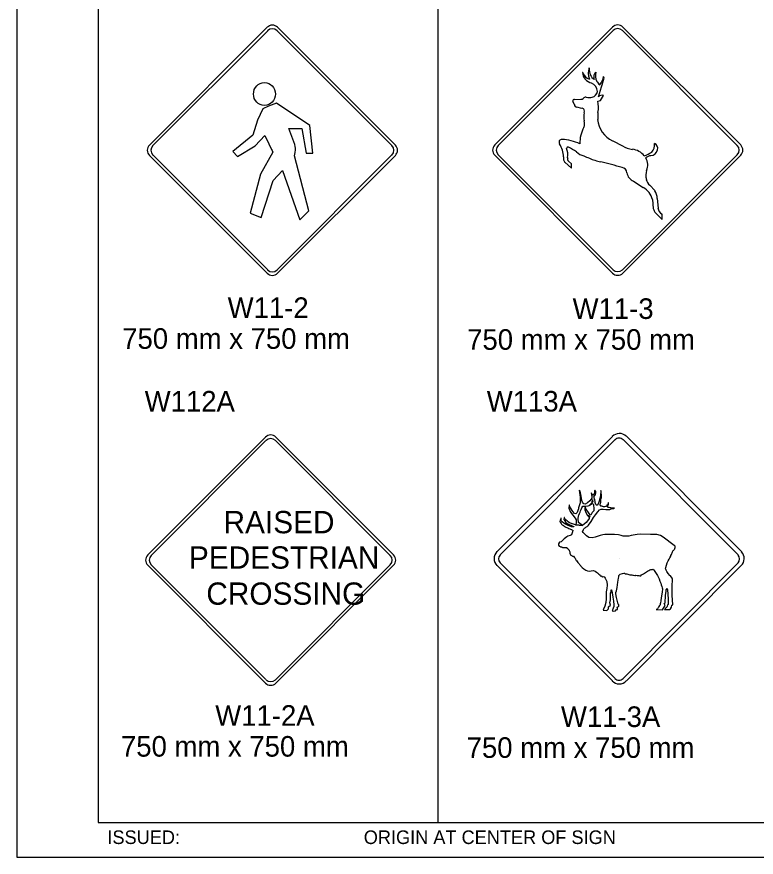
# Model space of a CAD drawing. Extents: x -12 to 6962, y -3756 to 679.
# Drawn here: x 2167.2 to 2275, y -235.4 to -112.9 of the extents above; entities that cross this region are included whole.
import ezdxf

# ---------------------------------------------------------------- set-up
doc = ezdxf.new("R2010")
doc.units = 0
for name, color, linetype in [('Level 1', 7, 'Continuous'), ('Level 2', 7, 'Continuous'), ('Level 3', 7, 'Continuous'), ('Level 62', 7, 'Continuous')]:
    doc.layers.add(name, color=color, linetype=linetype)

msp = doc.modelspace()

# ---------------------------------------------------------------- linework, layer by layer
at = {"layer": 'Level 1'}
for p, q in [((2179.04, -30.35), (2179.04, -230.35)), ((2228.56, -30.35), (2228.56, -230.35)), ((2186.51, -131.6), (2203.69, -114.41)), ((2187.01, -131.66), (2203.76, -114.91)), ((2205.13, -114.91), (2221.88, -131.66)), ((2205.19, -114.41), (2222.38, -131.6)), ((2236.88, -131.57), (2254.07, -114.39)), ((2237.38, -131.63), (2254.13, -114.88)), ((2255.5, -114.88), (2272.25, -131.63)), ((2255.56, -114.39), (2272.75, -131.57)), ((2252.02, -124.54), (2252.45, -123.1)), ((2248.49, -124.96), (2249.45, -124.9)), ((2252.3, -125.07), (2252.74, -124.35)), ((2248.51, -125.68), (2248.27, -125.21)), ((2249.6, -126.23), (2248.83, -126.04)), ((2251.89, -125.19), (2252.3, -125.07)), ((2254.08, -130.98), (2255.49, -131.68)), ((2204.46, -132.23), (2204.46, -132.23)), ((2254.83, -132.2), (2254.83, -132.2)), ((2203.69, -150.28), (2186.51, -133.09)), ((2203.76, -149.78), (2187.01, -133.03)), ((2221.88, -133.03), (2205.13, -149.78)), ((2222.38, -133.1), (2205.19, -150.28)), ((2254.07, -150.25), (2236.88, -133.07)), ((2254.13, -149.75), (2237.38, -133)), ((2272.25, -133), (2255.5, -149.76)), ((2272.75, -133.07), (2255.56, -150.25)), ((2248.08, -134.96), (2247.12, -134.1)), ((2248.08, -134.31), (2247.65, -133.92)), ((2248.08, -134.96), (2248.08, -134.31)), ((2257.12, -136.87), (2258.54, -137.76)), ((2259.49, -137.43), (2260.24, -138.23)), ((2259.88, -139.53), (2260, -140.82)), ((2260.56, -139.36), (2260.69, -140.76)), ((2260.37, -141.5), (2261.29, -142.43)), ((2261.29, -142.43), (2261.29, -141.68)), ((2186.26, -191.34), (2203.45, -174.16)), ((2186.76, -191.4), (2203.51, -174.65)), ((2204.88, -174.65), (2221.63, -191.4)), ((2204.94, -174.16), (2222.13, -191.34)), ((2237.22, -190.83), (2254.03, -174.08)), ((2237.68, -191.34), (2254.44, -174.53)), ((2255.62, -174.53), (2272.38, -191.34)), ((2256.08, -174.02), (2272.89, -190.88)), ((2251.17, -183.89), (2251.29, -183.99)), ((2247.14, -186.11), (2247.07, -185.95)), ((2247.28, -186.26), (2247.14, -186.11)), ((2247.42, -186.38), (2247.28, -186.26)), ((2247.57, -186.53), (2247.42, -186.38)), ((2247.8, -186.64), (2247.57, -186.53)), ((2248.05, -186.74), (2247.8, -186.64)), ((2248.37, -186.87), (2248.05, -186.74)), ((2248.66, -186.95), (2248.37, -186.87)), ((2249.65, -187.05), (2248.66, -186.95)), ((2204.21, -191.97), (2204.21, -191.97)), ((2255.14, -191.85), (2255.14, -191.85)), ((2203.45, -210.02), (2186.26, -192.84)), ((2203.51, -209.52), (2186.76, -192.77)), ((2221.63, -192.77), (2204.88, -209.53)), ((2222.13, -192.84), (2204.94, -210.02)), ((2254.03, -209.69), (2237.22, -192.88)), ((2254.44, -209.33), (2237.68, -192.47)), ((2272.38, -192.47), (2255.62, -209.33)), ((2272.84, -192.88), (2256.08, -209.69)), ((2254.39, -209.33), (2254.42, -209.35)), ((2179.04, -230.35), (2330.8, -230.35))]:
    msp.add_line(p, q, dxfattribs=at)
msp.add_lwpolyline([(2198.69, -132.5), (2199.36, -133.27), (2201.92, -131.68), (2203.35, -130.19), (2204.53, -132.6), (2202.69, -135.83), (2201.2, -141.52), (2202.79, -142.14), (2204.58, -136.75), (2205.92, -135.27), (2208.43, -142.49), (2209.76, -141.16), (2207.66, -133.17), (2207.76, -132.65), (2207.81, -132.3), (2207.81, -132.04), (2207.76, -131.78), (2207.71, -131.48), (2206.84, -129.17), (2208.73, -129.17), (2209.35, -132.76), (2210.32, -132.76), (2209.91, -128.71), (2205.04, -125.48), (2203.87, -125.89), (2203.05, -126.3), (2202.28, -127.94), (2201.61, -130.14)], close=True, dxfattribs=at)
for points in [[(2251.6, -182.11), (2251.55, -182.02), (2251.49, -181.9), (2251.43, -182.03), (2251.43, -182.32), (2251.25, -182.63), (2251.19, -182.64), (2251.16, -182.57), (2251.04, -182.43), (2251, -182.31), (2250.95, -182.26), (2250.98, -182.58), (2251.01, -182.63), (2251.02, -182.7), (2251.05, -183.01), (2251.05, -183.05), (2250.74, -183.45), (2250.39, -183.72), (2250.07, -183.92), (2249.88, -183.9), (2249.83, -183.86), (2249.66, -183.64), (2249.56, -183.38), (2249.48, -182.79), (2249.32, -182.02), (2249.2, -181.88), (2249.34, -182.92), (2249.34, -183.23), (2249.31, -183.44), (2249.32, -183.73), (2249.11, -184.45), (2249.1, -184.6), (2248.99, -184.86), (2248.88, -185.13), (2248.71, -185.35), (2248.51, -185.28), (2248.27, -185.02), (2247.94, -184.45), (2247.83, -184.32), (2247.8, -184.02), (2247.73, -184.1), (2247.7, -184.53), (2247.93, -185.08), (2248.62, -185.98), (2248.73, -186.21), (2248.73, -186.75), (2248.65, -186.95), (2249.66, -187.05), (2249.08, -186.6), (2249.02, -186.05), (2249.07, -185.62), (2249.13, -185.52), (2249.22, -185.29), (2249.32, -185.09), (2249.38, -184.93), (2249.47, -184.72), (2249.56, -184.47), (2249.71, -184.21), (2249.83, -184.23), (2250.18, -184.24), (2250.49, -184.19), (2250.66, -184.12), (2251.06, -183.69), (2251.14, -183.27), (2251.11, -183.32), (2251.12, -183.39), (2251.11, -183.45), (2251.12, -183.5), (2251.06, -183.7), (2251.05, -183.71), (2251.17, -183.57), (2251.17, -183.59), (2251.17, -183.59), (2250.68, -184.09), (2251.09, -183.85), (2251.17, -183.89)], [(2253.47, -183.73), (2253.47, -183.71), (2253.46, -183.7), (2253.42, -183.74), (2253.42, -183.8), (2253.42, -183.83), (2253.41, -183.88), (2253.36, -183.95), (2253.3, -184.02), (2253.24, -184.1), (2253.17, -184.18), (2253.15, -184.21), (2253.06, -184.28), (2253.03, -184.28), (2252.88, -184.3), (2252.88, -184.3), (2252.78, -184.3), (2252.76, -184.3), (2252.64, -184.29), (2252.57, -184.27), (2252.49, -184.25), (2252.46, -184.24), (2252.41, -184.22), (2252.36, -184.21), (2252.32, -184.18), (2252.29, -184.12), (2252.27, -184.1), (2252.27, -184.07), (2252.25, -184.03), (2252.25, -183.99), (2252.26, -183.93), (2252.29, -183.86), (2252.31, -183.76), (2252.34, -183.7), (2252.35, -183.62), (2252.36, -183.52), (2252.36, -183.43), (2252.36, -183.31), (2252.36, -183.2), (2252.37, -183.1), (2252.43, -183.04), (2252.43, -182.96), (2252.43, -182.75), (2252.43, -182.73), (2252.43, -182.64), (2252.43, -182.52), (2252.42, -182.41), (2252.42, -182.3), (2252.41, -182.21), (2252.39, -182.09), (2252.36, -182.01), (2252.35, -181.92), (2252.35, -181.92), (2252.35, -181.92), (2252.35, -181.99), (2252.35, -182.06), (2252.35, -182.11), (2252.34, -182.21), (2252.34, -182.24), (2252.34, -182.36), (2252.31, -182.45), (2252.28, -182.58), (2252.28, -182.67), (2252.28, -182.79), (2252.25, -182.88), (2252.23, -182.97), (2252.2, -183.1), (2252.18, -183.17), (2252.16, -183.23), (2252.14, -183.33), (2252.09, -183.5), (2251.98, -183.87), (2251.97, -183.87), (2251.94, -183.93), (2251.9, -183.98), (2251.87, -184.04), (2251.85, -184.08), (2251.78, -184.1), (2251.76, -184.1), (2251.7, -184.1), (2251.64, -183.96), (2251.55, -183.83), (2251.51, -183.69), (2251.51, -183.6), (2251.5, -183.5), (2251.48, -183.4), (2251.46, -183.29), (2251.42, -183.18), (2251.39, -183.04), (2251.38, -182.99), (2251.36, -182.92), (2251.34, -182.84), (2251.37, -182.79), (2251.42, -182.71), (2251.5, -182.63), (2251.55, -182.52), (2251.57, -182.41), (2251.6, -182.33), (2251.6, -182.23), (2251.6, -182.17), (2251.6, -182.11)], [(2262.02, -192.51), (2262.19, -192.19), (2262.3, -191.97), (2262.42, -191.77), (2262.57, -191.54), (2262.58, -191.43), (2262.64, -191.27), (2262.68, -191.12), (2262.74, -191.02), (2262.81, -190.9), (2262.86, -190.8), (2262.92, -190.7), (2262.98, -190.65), (2263.05, -190.55), (2263.14, -190.45), (2263.15, -190.42), (2263.16, -190.37), (2263.17, -190.3), (2263.18, -190.22), (2263.18, -190.14), (2263.18, -190.06), (2263.12, -190.01), (2263.06, -189.98), (2261.43, -188.74), (2261.03, -188.48), (2260.51, -188.35), (2259.61, -188.34), (2258.1, -188.33), (2257.63, -188.37), (2257.07, -188.47), (2256.75, -188.5), (2256.43, -188.61), (2255.61, -188.59), (2255.3, -188.52), (2254.93, -188.41), (2254.35, -188.37), (2253.28, -188.35), (2252.92, -188.37), (2252.63, -188.41), (2252.25, -188.49), (2251.98, -188.61), (2251.5, -188.77), (2251.08, -188.85), (2250.62, -188.8), (2250.25, -188.54), (2250.06, -188.35), (2249.97, -188.25), (2249.88, -188.14), (2249.82, -188.13), (2249.73, -188.07), (2249.7, -188), (2249.69, -187.88), (2249.76, -187.76), (2249.83, -187.63), (2249.87, -187.52), (2249.95, -187.43), (2250.04, -187.39), (2250.18, -187.29), (2250.24, -187.25), (2250.36, -187.17), (2250.43, -187.09), (2250.54, -187.05), (2250.56, -187.02), (2250.96, -186.46), (2251.29, -185.87), (2251.56, -185.47), (2251.92, -185.04), (2252.13, -184.76), (2252.38, -184.67), (2252.71, -184.64), (2253.09, -184.69), (2253.39, -184.71), (2253.68, -184.7), (2253.84, -184.63), (2254.05, -184.59), (2254.23, -184.55), (2254.29, -184.54), (2254.32, -184.52), (2254.33, -184.52), (2254.33, -184.51), (2254.2, -184.5), (2254.02, -184.5), (2253.89, -184.5), (2253.81, -184.49), (2253.73, -184.45), (2253.58, -184.44), (2253.48, -184.42), (2253.41, -184.4), (2253.39, -184.38), (2253.35, -184.33), (2253.34, -184.31), (2253.34, -184.27), (2253.34, -184.22), (2253.35, -184.17), (2253.39, -184.11), (2253.43, -184.07), (2253.47, -183.96), (2253.47, -183.9), (2253.47, -183.84), (2253.47, -183.77), (2253.47, -183.73)], [(2251.29, -183.99), (2251.33, -184.67), (2251.33, -184.66), (2251.33, -184.67), (2251.33, -184.82), (2251.31, -184.89), (2251.31, -184.89), (2251.22, -184.98), (2251.07, -185.13), (2250.88, -185.52), (2250.78, -185.51), (2250.32, -184.79), (2250.23, -184.67), (2250.15, -184.47), (2250.09, -184.47), (2250.07, -184.4), (2250.01, -184.41), (2250.01, -184.51), (2250, -184.64), (2250, -184.75), (2250.16, -185.14), (2250.42, -185.58), (2250.77, -185.75), (2250.41, -185.56), (2250.63, -185.9), (2250.64, -186.02), (2250.55, -186.19), (2250.21, -186.63), (2249.65, -187.05)], [(2247.07, -185.95), (2247.05, -185.9), (2246.98, -185.9), (2246.97, -186.17), (2247.08, -186.36), (2247.24, -186.59), (2247.42, -186.73), (2247.62, -186.86), (2247.84, -186.93), (2248, -187.01), (2248.18, -187.1), (2248.27, -187.16), (2248.37, -187.19), (2248.4, -187.19), (2248.4, -187.26), (2248.09, -187.23), (2247.58, -187.05), (2247.2, -186.85), (2246.94, -186.7), (2246.73, -186.52), (2246.57, -186.36), (2246.56, -186), (2246.51, -186), (2246.45, -186.15), (2246.41, -186.29), (2246.38, -186.44), (2246.42, -186.55), (2246.46, -186.63), (2246.54, -186.76), (2246.61, -186.85), (2246.7, -186.93), (2246.79, -187.01), (2246.88, -187.04), (2246.97, -187.1), (2247.09, -187.18), (2247.15, -187.23), (2247.26, -187.28), (2247.38, -187.34), (2247.53, -187.38), (2247.67, -187.46), (2247.81, -187.52), (2247.92, -187.57), (2248.06, -187.62), (2248.12, -187.67), (2248.23, -187.71), (2248.25, -187.74), (2248.23, -187.99), (2248.11, -188.24), (2248.05, -188.39), (2247.87, -188.5), (2247.53, -188.62), (2247.39, -188.69), (2247.02, -188.99), (2246.76, -189.25), (2246.57, -189.43), (2246.34, -189.49), (2246.17, -189.72), (2246.17, -189.9), (2246.29, -190.08), (2246.41, -190.13), (2246.48, -190.16), (2246.66, -190.16), (2246.67, -190.2), (2246.78, -190.26), (2247.13, -190.23), (2247.33, -190.25), (2247.55, -190.4), (2247.6, -190.48), (2247.66, -190.58), (2247.72, -190.65), (2247.75, -190.71), (2247.78, -190.8), (2247.81, -190.9), (2247.81, -190.97), (2247.81, -191.04), (2247.85, -191.16), (2247.87, -191.19), (2247.89, -191.22), (2247.94, -191.31), (2247.96, -191.35), (2248, -191.39), (2248.07, -191.42), (2248.08, -191.44), (2248.17, -191.48), (2248.18, -191.49), (2248.23, -191.5), (2248.26, -191.5), (2248.3, -191.5), (2248.34, -191.5), (2248.36, -191.5), (2248.37, -191.5), (2248.44, -191.64), (2248.61, -191.82), (2248.67, -191.94), (2248.77, -192.13), (2248.82, -192.17), (2248.99, -192.43), (2249.19, -192.65), (2249.24, -192.71), (2249.64, -193.16), (2249.88, -193.38)], [(2249.88, -193.38), (2250.14, -193.56), (2250.41, -193.65), (2250.68, -193.68), (2250.93, -193.66), (2251.27, -193.61), (2251.53, -193.7), (2251.73, -193.84), (2251.88, -193.96), (2252.07, -194.15), (2252.18, -194.23), (2252.22, -194.29), (2252.25, -194.33), (2252.25, -194.38), (2252.4, -194.36), (2252.65, -194.51), (2252.79, -194.49), (2252.89, -194.59), (2252.97, -194.74), (2253.22, -195.23), (2253.25, -195.74), (2253.2, -196.24), (2253.15, -196.73), (2253.11, -197.72), (2253.1, -198.28), (2252.91, -198.8), (2252.75, -199.23), (2252.68, -199.39), (2253.23, -199.44), (2253.47, -199.17), (2253.46, -198.91), (2253.74, -198.67), (2253.65, -198.34), (2253.74, -197.9), (2253.77, -197.24), (2253.76, -196.92), (2253.84, -196.76), (2253.85, -196.53), (2253.87, -196.42), (2253.89, -196.4), (2253.99, -196.86), (2254.1, -197.47), (2254.18, -198.1), (2254.26, -198.63), (2254.22, -198.84), (2254.15, -199.12), (2254.1, -199.26), (2254.06, -199.34), (2254.06, -199.39), (2253.99, -199.5), (2254.26, -199.54), (2254.48, -199.5), (2254.57, -199.32), (2254.69, -199.28), (2254.76, -199.28), (2254.76, -199.02), (2254.73, -198.99), (2254.74, -198.95), (2254.85, -198.91), (2254.94, -198.85), (2254.99, -198.79), (2254.99, -198.76), (2254.98, -198.66), (2254.95, -198.58), (2254.9, -198.5), (2254.74, -197.95), (2254.63, -197.55), (2254.6, -197.28), (2254.55, -196.94), (2254.55, -196.82), (2254.62, -196.55), (2254.71, -196.06), (2254.83, -195.33), (2254.92, -194.73), (2254.95, -194.51), (2254.98, -194.33), (2255.06, -194.23), (2255.11, -194.18), (2255.17, -194.16)], [(2255.17, -194.16), (2255.51, -194.05), (2255.68, -194), (2255.79, -194.01), (2255.88, -194.08), (2256, -194.08), (2256.13, -194.09), (2256.27, -194.16), (2256.42, -194.2), (2256.56, -194.23), (2256.71, -194.24), (2256.86, -194.26), (2257, -194.27), (2257.12, -194.29), (2257.29, -194.33), (2257.39, -194.33), (2257.47, -194.3), (2257.67, -194.31), (2257.79, -194.31), (2257.88, -194.34), (2258.04, -194.37), (2258.13, -194.39), (2258.17, -194.39), (2258.29, -194.22), (2258.57, -194.07), (2258.86, -193.88), (2259.17, -193.72), (2259.33, -193.59), (2259.51, -193.53), (2259.66, -193.47), (2259.73, -193.46), (2259.82, -193.46), (2259.87, -193.44), (2259.96, -193.41), (2260.12, -193.59), (2260.34, -193.9), (2260.61, -194.32), (2260.84, -194.83), (2260.97, -195.14), (2261.08, -195.47), (2261.15, -195.7), (2261.24, -195.93), (2261.31, -196.14), (2261.34, -196.3), (2261.31, -196.74), (2261.14, -197.59), (2261.11, -198.05), (2261.07, -198.3), (2261.02, -198.46), (2260.98, -198.59), (2260.92, -198.72), (2260.83, -198.86), (2260.75, -198.99), (2260.67, -199.1), (2260.6, -199.17), (2260.55, -199.23), (2260.44, -199.3), (2261.32, -199.32), (2261.72, -198.73), (2261.58, -198.44), (2261.71, -198.32), (2261.78, -197.24), (2261.86, -196.62), (2261.87, -196.41), (2262, -196.22), (2262.03, -196.28), (2262.07, -196.44), (2262.16, -197.73), (2262.15, -198.54), (2262.06, -198.63), (2262.02, -198.81), (2261.95, -198.96), (2261.91, -199.02), (2261.83, -199.07), (2261.79, -199.14), (2261.76, -199.16), (2261.72, -199.24), (2261.69, -199.25), (2261.64, -199.3), (2262.37, -199.29), (2262.52, -199.19), (2262.64, -198.94), (2262.68, -198.67), (2262.83, -198.6), (2262.75, -197.22), (2262.74, -196.28), (2262.73, -195.64), (2262.81, -195.15), (2262.8, -194.88), (2262.73, -194.73), (2262.67, -194.6), (2262.61, -194.51), (2262.5, -194.39), (2262.4, -194.34), (2262.16, -194.03), (2261.95, -193.75), (2261.88, -193.54), (2261.82, -193.43), (2261.8, -193.38), (2261.83, -193.16), (2262.02, -192.51)]]:
    msp.add_lwpolyline(points, dxfattribs=at)
for centre, radius, start, end in [((2204.44, -115.16), 1.06, 45, 135), ((2204.44, -115.6), 0.969, 45, 135), ((2254.81, -115.13), 1.06, 45, 135), ((2254.81, -115.57), 0.969, 45, 135), ((2251.43, -120.8), 1.79, 186.2879, 255.6045), ((2249.62, -121.19), 0.201, 30.1048, 80.5121), ((2250.92, -120.83), 1.16, 193.2507, 257.6268), ((2253.04, -121.08), 2.52, 162.0635, 200.2931), ((2250.55, -120.39), 0.123, 347.4048, 46.932), ((2252.42, -120.61), 1.76, 173.8726, 234.3252), ((2252.35, -121.65), 1.04, 153.1097, 202.0619), ((2252.83, -121.98), 1.61, 139.8512, 150.2463), ((2253.97, -121.35), 2.41, 170.1883, 203.1194), ((2253.76, -121.04), 2.37, 212.0666, 228.2156), ((2250.43, -121.29), 2.32, 319.129, 352.9872), ((2242.97, -119.6), 10.1, 339.7331, 347.2939), ((2252.48, -121.8), 0.34, 356.6035, 43.1712), ((2250.45, -123.85), 1.42, 3.413, 67.7627), ((2248.45, -125.14), 0.19, 75.6178, 199.8309), ((2249.48, -124.46), 0.442, 265.6838, 309.921), ((2250.11, -125.01), 0.411, 75.3801, 148.2178), ((2250.65, -122.1), 2.56, 260.3156, 279.6844), ((2250.77, -123.54), 1.12, 285.7232, 348.2197), ((2252.56, -125.12), 0.799, 76.8953, 132.8591), ((2248.82, -125.73), 0.314, 171.1326, 273.231), ((2248.48, -126.08), 3.53, 347.8263, 14.5629), ((2249.55, -126.65), 0.432, 331.6314, 83.1268), ((2252.54, -127.51), 2.69, 166.0399, 191.7998), ((2257.92, -127.53), 6.03, 173.2489, 182.9419), ((2248.67, -128.48), 1.31, 337.1065, 18.7134), ((2255.73, -127.5), 3.86, 185.1556, 244.5783), ((2253.91, -131.25), 4.62, 150.7089, 181.8526), ((2246.65, -131.17), 0.403, 84.4364, 219.3147), ((2246.32, -137.92), 7.16, 65.5164, 87.0001), ((2187.26, -132.35), 1.06, 135, 225), ((2187.69, -132.35), 0.969, 135, 225), ((2221.19, -132.35), 0.969, 315, 45), ((2221.63, -132.35), 1.06, 315, 45), ((2237.63, -132.32), 1.06, 135, 225), ((2238.06, -132.32), 0.969, 135, 225), ((2243.4, -133.34), 3.51, 0.339, 33.0043), ((2247.52, -132.06), 0.173, 59.5142, 183.1577), ((2245.16, -133.01), 2.38, 349.9801, 23.3277), ((2244.91, -138.02), 6.68, 54.3742, 66.1366), ((2257.29, -128.94), 3.29, 236.723, 264.0247), ((2256.67, -134.74), 2.55, 38.4441, 83.6572), ((2259.58, -132.07), 1.06, 273.4749, 347.9539), ((2258.62, -131.58), 1.55, 317.864, 8.3583), ((2259.88, -132.07), 0.77, 343.3834, 69.1935), ((2271.56, -132.32), 0.969, 315, 45), ((2272, -132.32), 1.06, 315, 45), ((2247.78, -133.51), 0.89, 167.6485, 222.0897), ((2247.91, -133.59), 0.429, 158.2276, 232.2927), ((2250.25, -131.15), 2.04, 224.7048, 258.76), ((2256.54, -118.55), 16.06, 245.385, 248.5882), ((2253.96, -126.02), 8.17, 246.3466, 258.4461), ((2257.26, -128.81), 4.57, 287.9379, 303.3439), ((2259.69, -134.2), 1.07, 92.2258, 136.7886), ((2257.34, -134.45), 1.85, 333.6908, 32.0917), ((2238.03, -193.03), 60.71, 73.3151, 76.3817), ((2255.37, -135.65), 0.779, 2.8143, 83.5521), ((2257.77, -135.36), 1.64, 188.8313, 246.7001), ((2261.56, -135.98), 2.65, 164.4551, 193.6044), ((2260.52, -136.23), 1.59, 193.8134, 229.481), ((2257.15, -140.22), 2.82, 14.1231, 60.5487), ((2258.57, -139.33), 2, 359.1017, 33.2215), ((2261.24, -140.58), 1.26, 190.9492, 226.6687), ((2261.85, -140.65), 1.17, 185.1332, 241.2242), ((2204.44, -149.53), 1.06, 225, 315), ((2204.44, -149.1), 0.969, 225, 315), ((2254.81, -149.51), 1.06, 225, 315), ((2254.81, -149.07), 0.969, 225, 315), ((2204.2, -174.9), 1.06, 45, 135), ((2255.06, -175.06), 1.43, 45.9756, 136.9051), ((2204.2, -175.34), 0.969, 45, 135), ((2255.01, -175.13), 0.827, 44.5353, 135.4647), ((2238.24, -191.87), 1.46, 135.3838, 224.6162), ((2271.83, -191.86), 1.43, 313.7033, 42.6894), ((2187.01, -192.09), 1.06, 135, 225), ((2187.45, -192.09), 0.969, 135, 225), ((2220.95, -192.09), 0.969, 315, 45), ((2221.38, -192.09), 1.06, 315, 45), ((2238.23, -191.92), 0.803, 135.3838, 224.6162), ((2271.78, -191.92), 0.81, 315.3143, 44.3004), ((2255, -208.76), 0.835, 222.766, 315.3045), ((2204.2, -209.28), 1.06, 225, 315), ((2204.2, -208.84), 0.969, 225, 315), ((2255.03, -208.72), 1.42, 223.7308, 316.2692)]:
    msp.add_arc(centre, radius, start, end, dxfattribs=at)
msp.add_ellipse((2203.29, -124.14), major_axis=(0, 1.68), ratio=0.957031, dxfattribs=at)
at = {"layer": 'Level 62'}
msp.add_lwpolyline([(2167.17, -235.4), (2342.43, -235.4), (2342.43, -22.31), (2167.17, -22.31)], close=True, dxfattribs=at)

# ---------------------------------------------------------------- texts
at = {"layer": 'Level 1'}
for s, p in [('RAISED', (2197.32, -188.18)), ('PEDESTRIAN', (2192.27, -193.34)), ('CROSSING', (2194.81, -198.6))]:
    msp.add_text(s, height=3.25, dxfattribs=at).set_placement(p)
at = {"layer": 'Level 2'}
for s, p in [('W112A', (2185.82, -170.43)), ('W113A', (2235.71, -170.43))]:
    msp.add_text(s, height=3, dxfattribs=at).set_placement(p)
at = {"layer": 'Level 3'}
for s, height, p in [('W11-2', 3, (2197.92, -156.79)), ('W11-3', 3, (2248.23, -156.93)), ('750 mm x 750 mm', 3, (2182.54, -161.29)), ('750 mm x 750 mm', 3, (2232.85, -161.43)), ('W11-2A', 3, (2196.11, -216.24)), ('W11-3A', 3, (2246.53, -216.42)), ('750 mm x 750 mm', 3, (2182.36, -220.74)), ('750 mm x 750 mm', 3, (2232.78, -220.92)), ('ISSUED:', 1.98, (2180.38, -233.48)), ('ORIGIN AT CENTER OF SIGN', 1.9795, (2217.77, -233.48))]:
    msp.add_text(s, height=height, dxfattribs=at).set_placement(p)

doc.saveas('drawing.dxf')
